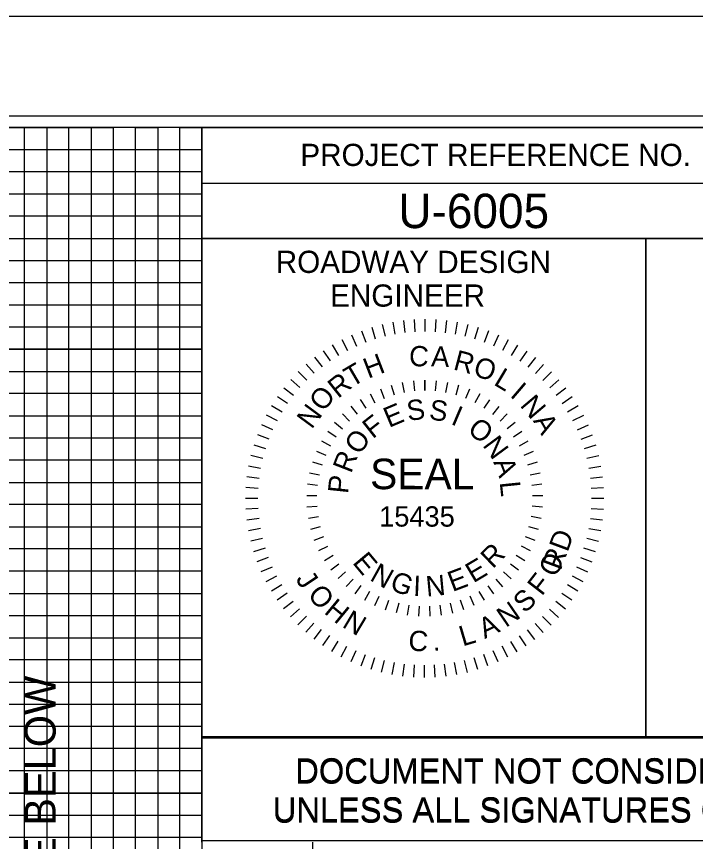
# Model space of a CAD drawing. Extents: x 1626113 to 1628102, y 900759 to 901859.
# Drawn here: x 1627538.1 to 1627691.2, y 901673.3 to 901859.2 of the extents above; entities that cross this region are included whole.
import ezdxf

# ---------------------------------------------------------------- set-up
doc = ezdxf.new("R2010")
doc.units = 0
for name, color, linetype in [('Matchline Text', 7, 'Continuous'), ('Old_Level_21', 7, 'Continuous'), ('Prop Plan Preparation Cover Label', 7, 'Continuous'), ('Sheet Cutting Line CELL', 7, 'Continuous'), ('Sheet Data Field CELL', 7, 'Continuous'), ('Sheet DOT Grid CELL', 7, 'Continuous'), ('Sheet Plot Border Inside CELL', 7, 'Continuous'), ('Sheet Plot Border Outside CELL', 7, 'Continuous'), ('Sheet Profile CELL', 7, 'Continuous'), ('Sheet Profile Grid Major CELL', 7, 'Continuous'), ('Sheet Profile Grid Middle CELL', 7, 'Continuous'), ('Sheet Sticker Exception Certification CELL', 7, 'Continuous')]:
    doc.layers.add(name, color=color, linetype=linetype)

msp = doc.modelspace()

# ---------------------------------------------------------------- linework, layer by layer
at = {"layer": 'Old_Level_21'}
for p, q in [((1627625.33, 901790.68), (1627625.66, 901787.95)), ((1627627.76, 901790.9), (1627627.92, 901788.15)), ((1627630.2, 901790.97), (1627630.2, 901788.22)), ((1627632.64, 901790.89), (1627632.47, 901788.15)), ((1627635.07, 901790.67), (1627634.73, 901787.94)), ((1627618.19, 901789.16), (1627619, 901786.53)), ((1627620.54, 901789.81), (1627621.19, 901787.14)), ((1627622.92, 901790.32), (1627623.41, 901787.61)), ((1627637.48, 901790.3), (1627636.98, 901787.6)), ((1627639.86, 901789.79), (1627639.2, 901787.12)), ((1627642.21, 901789.13), (1627641.39, 901786.5)), ((1627613.63, 901787.44), (1627614.75, 901784.93)), ((1627615.88, 901788.37), (1627616.86, 901785.79)), ((1627644.51, 901788.33), (1627643.53, 901785.76)), ((1627646.76, 901787.39), (1627645.63, 901784.88)), ((1627609.31, 901785.18), (1627610.73, 901782.82)), ((1627611.43, 901786.38), (1627612.71, 901783.93)), ((1627648.95, 901786.32), (1627647.67, 901783.89)), ((1627651.08, 901785.12), (1627649.65, 901782.77)), ((1627607.26, 901783.86), (1627608.82, 901781.59)), ((1627653.12, 901783.79), (1627651.56, 901781.53)), ((1627605.29, 901782.42), (1627606.99, 901780.25)), ((1627655.08, 901782.35), (1627653.38, 901780.18)), ((1627603.42, 901780.86), (1627605.24, 901778.79)), ((1627656.95, 901780.78), (1627655.13, 901778.73)), ((1627601.64, 901779.19), (1627603.58, 901777.24)), ((1627658.73, 901779.11), (1627656.78, 901777.17)), ((1627599.97, 901777.42), (1627602.02, 901775.59)), ((1627622.57, 901776.11), (1627623.22, 901773.91)), ((1627625.07, 901776.72), (1627625.5, 901774.47)), ((1627627.61, 901777.09), (1627627.83, 901774.81)), ((1627630.18, 901777.21), (1627630.18, 901774.92)), ((1627630.18, 901774.92), (1627630.18, 901777.21)), ((1627632.75, 901777.08), (1627632.53, 901774.8)), ((1627635.29, 901776.71), (1627634.85, 901774.46)), ((1627637.79, 901776.09), (1627637.13, 901773.89)), ((1627660.4, 901777.33), (1627658.33, 901775.51)), ((1627598.4, 901775.54), (1627600.56, 901773.84)), ((1627617.81, 901774.18), (1627618.87, 901772.15)), ((1627620.14, 901775.26), (1627621.01, 901773.13)), ((1627640.21, 901775.23), (1627639.34, 901773.11)), ((1627642.54, 901774.14), (1627641.47, 901772.12)), ((1627661.96, 901775.45), (1627659.79, 901773.76)), ((1627596.95, 901773.58), (1627599.21, 901772.02)), ((1627615.59, 901772.88), (1627616.85, 901770.96)), ((1627644.76, 901772.84), (1627643.5, 901770.92)), ((1627663.4, 901773.49), (1627661.13, 901771.93)), ((1627595.63, 901771.54), (1627597.98, 901770.11)), ((1627613.51, 901771.37), (1627614.95, 901769.58)), ((1627646.83, 901771.32), (1627645.39, 901769.54)), ((1627664.72, 901771.44), (1627662.36, 901770.02)), ((1627594.42, 901769.41), (1627596.86, 901768.13)), ((1627611.59, 901769.67), (1627613.19, 901768.02)), ((1627648.75, 901769.62), (1627647.15, 901767.98)), ((1627665.92, 901769.31), (1627663.47, 901768.04)), ((1627593.36, 901767.22), (1627595.86, 901766.09)), ((1627609.83, 901767.79), (1627611.58, 901766.31)), ((1627650.5, 901767.73), (1627648.75, 901766.26)), ((1627666.97, 901767.12), (1627664.47, 901766)), ((1627592.42, 901764.97), (1627594.99, 901763.99)), ((1627608.27, 901765.75), (1627610.15, 901764.44)), ((1627652.06, 901765.69), (1627650.17, 901764.38)), ((1627667.91, 901764.87), (1627665.33, 901763.89)), ((1627606.91, 901763.57), (1627608.91, 901762.45)), ((1627653.41, 901763.5), (1627651.41, 901762.39)), ((1627591.62, 901762.67), (1627594.25, 901761.85)), ((1627605.77, 901761.26), (1627607.87, 901760.34)), ((1627654.55, 901761.19), (1627652.45, 901760.28)), ((1627668.7, 901762.56), (1627666.07, 901761.75)), ((1627590.96, 901760.32), (1627593.63, 901759.66)), ((1627669.35, 901760.21), (1627666.68, 901759.56)), ((1627590.45, 901757.94), (1627593.15, 901757.44)), ((1627604.85, 901758.86), (1627607.03, 901758.15)), ((1627655.46, 901758.79), (1627653.27, 901758.09)), ((1627669.86, 901757.82), (1627667.15, 901757.33)), ((1627590.08, 901755.53), (1627592.81, 901755.19)), ((1627604.17, 901756.38), (1627606.41, 901755.88)), ((1627656.13, 901756.31), (1627653.89, 901755.82)), ((1627670.22, 901755.41), (1627667.49, 901755.09)), ((1627603.74, 901753.85), (1627606.01, 901753.57)), ((1627656.56, 901753.77), (1627654.28, 901753.5)), ((1627589.85, 901753.1), (1627592.6, 901752.93)), ((1627670.44, 901752.99), (1627667.69, 901752.83)), ((1627589.78, 901750.66), (1627592.53, 901750.66)), ((1627603.55, 901751.28), (1627605.84, 901751.22)), ((1627656.74, 901751.21), (1627654.45, 901751.16)), ((1627670.51, 901750.55), (1627667.76, 901750.55)), ((1627589.85, 901748.22), (1627592.59, 901748.38)), ((1627603.6, 901748.71), (1627605.89, 901748.88)), ((1627656.68, 901748.64), (1627654.39, 901748.81)), ((1627670.43, 901748.11), (1627667.69, 901748.28)), ((1627590.07, 901745.79), (1627592.79, 901746.12)), ((1627603.91, 901746.16), (1627606.17, 901746.54)), ((1627654.12, 901746.56), (1627656.38, 901746.17)), ((1627604.46, 901743.65), (1627606.67, 901744.25)), ((1627655.81, 901743.58), (1627653.6, 901744.18)), ((1627670.21, 901745.68), (1627667.48, 901746.02)), ((1627590.43, 901743.38), (1627593.13, 901743.87)), ((1627669.84, 901743.27), (1627667.14, 901743.77)), ((1627590.93, 901741), (1627593.61, 901741.65)), ((1627605.25, 901741.2), (1627607.4, 901742.01)), ((1627655.01, 901741.13), (1627652.86, 901741.95)), ((1627669.33, 901740.89), (1627666.66, 901741.55)), ((1627591.59, 901738.65), (1627594.22, 901739.46)), ((1627606.28, 901738.85), (1627608.33, 901739.86)), ((1627653.97, 901738.78), (1627651.92, 901739.8)), ((1627668.67, 901738.54), (1627666.04, 901739.36)), ((1627592.38, 901736.34), (1627594.95, 901737.32)), ((1627607.52, 901736.6), (1627609.47, 901737.8)), ((1627652.73, 901736.54), (1627650.78, 901737.74)), ((1627667.87, 901736.24), (1627665.3, 901737.22)), ((1627593.31, 901734.09), (1627595.82, 901735.21)), ((1627608.98, 901734.48), (1627610.81, 901735.87)), ((1627651.26, 901734.42), (1627649.44, 901735.81)), ((1627666.93, 901733.99), (1627664.42, 901735.12)), ((1627594.37, 901731.89), (1627596.81, 901733.17)), ((1627610.64, 901732.51), (1627612.32, 901734.07)), ((1627649.6, 901732.46), (1627647.93, 901734.02)), ((1627665.86, 901731.79), (1627663.43, 901733.08)), ((1627595.57, 901729.77), (1627597.92, 901731.19)), ((1627612.47, 901730.72), (1627614, 901732.43)), ((1627647.76, 901730.67), (1627646.24, 901732.38)), ((1627614.48, 901729.1), (1627615.83, 901730.95)), ((1627616.62, 901727.69), (1627617.79, 901729.67)), ((1627643.6, 901727.65), (1627642.44, 901729.63)), ((1627645.75, 901729.06), (1627644.41, 901730.92)), ((1627664.66, 901729.67), (1627662.31, 901731.1)), ((1627596.89, 901727.72), (1627599.16, 901729.28)), ((1627598.33, 901725.76), (1627600.5, 901727.45)), ((1627618.9, 901726.49), (1627619.87, 901728.57)), ((1627621.28, 901725.52), (1627622.05, 901727.68)), ((1627638.94, 901725.49), (1627638.18, 901727.66)), ((1627641.32, 901726.46), (1627640.36, 901728.54)), ((1627663.33, 901727.63), (1627661.07, 901729.19)), ((1627599.89, 901723.88), (1627601.95, 901725.7)), ((1627624.28, 901727.01), (1627623.72, 901724.78)), ((1627626.26, 901724.28), (1627626.6, 901726.55)), ((1627628.82, 901724.03), (1627628.93, 901726.32)), ((1627631.39, 901724.03), (1627631.29, 901726.32)), ((1627633.95, 901724.27), (1627633.62, 901726.54)), ((1627636.47, 901724.76), (1627635.93, 901726.99)), ((1627660.32, 901723.79), (1627658.27, 901725.62)), ((1627661.89, 901725.67), (1627659.72, 901727.36)), ((1627601.56, 901722.1), (1627603.51, 901724.04)), ((1627658.65, 901722.02), (1627656.7, 901723.97)), ((1627603.33, 901720.43), (1627605.16, 901722.48)), ((1627656.87, 901720.35), (1627655.05, 901722.41)), ((1627605.21, 901718.86), (1627606.9, 901721.02)), ((1627654.99, 901718.79), (1627653.3, 901720.96)), ((1627607.17, 901717.41), (1627608.73, 901719.68)), ((1627609.21, 901716.09), (1627610.64, 901718.44)), ((1627650.98, 901716.03), (1627649.56, 901718.38)), ((1627653.03, 901717.35), (1627651.47, 901719.62)), ((1627611.33, 901714.89), (1627612.62, 901717.32)), ((1627613.53, 901713.82), (1627614.66, 901716.32)), ((1627646.66, 901713.77), (1627645.54, 901716.28)), ((1627648.85, 901714.83), (1627647.58, 901717.27)), ((1627615.78, 901712.88), (1627616.76, 901715.45)), ((1627618.08, 901712.08), (1627618.9, 901714.71)), ((1627642.1, 901712.05), (1627641.29, 901714.68)), ((1627644.4, 901712.84), (1627643.43, 901715.41)), ((1627620.43, 901711.42), (1627621.09, 901714.09)), ((1627622.81, 901710.91), (1627623.31, 901713.61)), ((1627625.22, 901710.54), (1627625.56, 901713.27)), ((1627627.65, 901710.31), (1627627.82, 901713.06)), ((1627630.09, 901710.24), (1627630.09, 901712.99)), ((1627632.53, 901710.31), (1627632.37, 901713.05)), ((1627634.95, 901710.53), (1627634.63, 901713.26)), ((1627637.36, 901710.89), (1627636.87, 901713.59)), ((1627639.75, 901711.39), (1627639.1, 901714.07))]:
    msp.add_line(p, q, dxfattribs=at)
at = {"layer": 'Prop Plan Preparation Cover Label'}
for p, q in [((1626329.95, 901829.2), (1627579.95, 901829.2)), ((1627579.95, 901824.2), (1626329.95, 901823.85)), ((1626329.95, 901819.2), (1627579.95, 901819.2)), ((1627579.9, 901699.2), (1626329.95, 901699.2)), ((1627579.95, 901694.2), (1626329.95, 901694.2)), ((1627579.95, 901689.2), (1626329.95, 901689.2)), ((1626329.95, 901679.2), (1627579.95, 901679.2)), ((1627579.95, 901674.2), (1626329.95, 901674.2))]:
    msp.add_line(p, q, dxfattribs=at)
for points in [[(1627534.95, 901334.2), (1627539.95, 901334.2), (1627539.95, 901834.2), (1627544.95, 901834.2), (1627544.95, 901334.2), (1627549.95, 901334.2), (1627549.95, 901834.2), (1627559.95, 901834.2), (1627559.95, 901334.2), (1627564.95, 901334.2), (1627564.95, 901834.2), (1627569.95, 901834.2), (1627569.95, 901334.2), (1627574.95, 901334.2), (1627574.95, 901834.2), (1627584.95, 901834.2)], [(1627579.95, 901814.2), (1626329.95, 901814.2), (1626329.95, 901804.2), (1627579.95, 901804.2)], [(1627579.9, 901799.2), (1626329.95, 901799.2), (1626329.95, 901794.2), (1627579.95, 901794.2)], [(1627579.95, 901789.2), (1626329.95, 901789.2), (1626329.95, 901779.2), (1627579.95, 901779.2)], [(1627579.95, 901774.2), (1626329.95, 901774.2), (1626329.95, 901769.2), (1627579.95, 901769.2)], [(1627579.95, 901764.2), (1626329.95, 901764.2), (1626329.95, 901754.2), (1627579.95, 901754.2)], [(1627579.95, 901749.2), (1626329.95, 901749.2), (1626329.95, 901744.2), (1627579.95, 901744.2)], [(1627579.95, 901739.2), (1626329.95, 901739.2), (1626329.95, 901729.2), (1627579.95, 901729.2)], [(1627579.95, 901724.1), (1626330.05, 901724.1), (1626330.05, 901719.2), (1627579.95, 901719.2)], [(1627579.95, 901714.2), (1626329.95, 901714.2), (1626329.95, 901704.2), (1627579.95, 901704.2)]]:
    msp.add_lwpolyline(points, dxfattribs=at)
at = {"layer": 'Sheet Cutting Line CELL'}
msp.add_line((1627796.95, 901859.2), (1626112.95, 901859.2), dxfattribs=at)
at = {"layer": 'Sheet DOT Grid CELL'}
for p, q in [((1627579.9, 901784.2), (1626279.95, 901784.2)), ((1627579.9, 901734.2), (1626279.95, 901734.2)), ((1627579.95, 901334.2), (1627579.95, 901696.65)), ((1627579.95, 901684.2), (1626279.95, 901684.2))]:
    msp.add_line(p, q, dxfattribs=at)
at = {"layer": 'Sheet Plot Border Inside CELL'}
msp.add_lwpolyline([(1626125.95, 900781.65), (1627792.45, 900781.65), (1627792.45, 901836.75), (1626125.95, 901836.75)], close=True, dxfattribs=at)
at = {"layer": 'Sheet Plot Border Outside CELL'}
msp.add_lwpolyline([(1626112.95, 900759.2), (1627796.95, 900759.2), (1627796.95, 901859.2), (1626112.95, 901859.2)], close=True, dxfattribs=at)
at = {"layer": 'Sheet Profile CELL'}
for p, q in [((1627579.9, 901821.65), (1627779.95, 901821.65)), ((1627679.95, 901809.15), (1627679.95, 901696.7))]:
    msp.add_line(p, q, dxfattribs=at)
for points in [[(1627779.95, 901834.2), (1626279.95, 901834.2), (1626279.95, 900784.2), (1627779.95, 900784.2)], [(1627579.9, 901834.2), (1627779.95, 901834.2), (1627779.95, 901809.15), (1627579.9, 901809.15)], [(1627579.9, 901809.15), (1627679.95, 901809.15), (1627679.95, 901696.65), (1627579.9, 901696.65)], [(1627679.95, 901809.15), (1627779.95, 901809.15), (1627779.95, 901696.65), (1627679.95, 901696.65)]]:
    msp.add_lwpolyline(points, close=True, dxfattribs=at)
at = {"layer": 'Sheet Profile Grid Major CELL'}
for points in [[(1627129.95, 901334.2), (1627179.95, 901334.2), (1627179.95, 901834.2), (1627229.95, 901834.2), (1627229.95, 901334.2), (1627279.95, 901334.2), (1627279.95, 901834.2), (1627329.95, 901834.2), (1627329.95, 901334.2), (1627379.95, 901334.2), (1627379.95, 901834.2), (1627429.95, 901834.2), (1627429.95, 901334.2), (1627479.95, 901334.2), (1627479.95, 901834.2), (1627529.95, 901834.2), (1627529.95, 901334.2), (1627579.95, 901334.2), (1627579.95, 901834.2), (1627606.25, 901834.2)], [(1626279.95, 901784.2), (1627579.95, 901784.2)], [(1627579.95, 901734.2), (1626279.95, 901734.2), (1626279.95, 901684.2), (1627579.95, 901684.2)]]:
    msp.add_lwpolyline(points, dxfattribs=at)
at = {"layer": 'Sheet Profile Grid Middle CELL'}
msp.add_line((1626279.95, 901809.2), (1627579.9, 901809.2), dxfattribs=at)
for points in [[(1627104.95, 901834.2), (1627154.95, 901834.2), (1627154.95, 901334.2), (1627204.95, 901334.2), (1627204.95, 901834.2), (1627254.95, 901834.2), (1627254.95, 901334.2), (1627304.95, 901334.2), (1627304.95, 901834.2), (1627354.95, 901834.2), (1627354.95, 901334.2), (1627404.95, 901334.2), (1627404.95, 901834.2), (1627454.95, 901834.2), (1627454.95, 901334.2), (1627504.95, 901334.2), (1627504.95, 901834.2), (1627554.95, 901834.2), (1627554.95, 901334.2), (1627604.95, 901334.2), (1627604.95, 901673.15)], [(1627579.95, 901759.2), (1626279.95, 901759.2), (1626279.95, 901709.2), (1627579.95, 901709.2)]]:
    msp.add_lwpolyline(points, dxfattribs=at)
at = {"layer": 'Sheet Sticker Exception Certification CELL'}
for p, q in [((1627579.9, 901673.4), (1627579.9, 901696.9)), ((1627579.9, 901696.9), (1627779.93, 901696.9)), ((1627579.9, 901673.4), (1627579.9, 901696.9)), ((1627579.9, 901696.9), (1627779.93, 901696.9)), ((1627579.9, 901673.15), (1627579.9, 901696.65)), ((1627579.9, 901696.65), (1627779.93, 901696.65)), ((1627579.9, 901673.15), (1627579.9, 901696.65)), ((1627579.9, 901696.65), (1627779.93, 901696.65)), ((1627779.93, 901673.4), (1627579.9, 901673.4)), ((1627779.93, 901673.4), (1627579.9, 901673.4))]:
    msp.add_line(p, q, dxfattribs=at)

# ---------------------------------------------------------------- texts
at = {"layer": 'Matchline Text'}
msp.add_text('MATCH LINE -L- STA 50+00.00 SEE BELOW', height=7, rotation=90, dxfattribs=at).set_placement((1627546.95, 901519.45))
at = {"layer": 'Old_Level_21'}
for s, height, rotation, p in [('H', 4.58, 20.9878, (1627617.4, 901777.54)), ('C', 4.58, 357.2771, (1627626.52, 901780.47)), ('A', 4.58, 357.2771, (1627631.53, 901780.37)), ('R', 4.58, 345.2678, (1627636.38, 901779.69)), ('O', 4.58, 342.211, (1627640.82, 901778.36)), ('T', 4.58, 30.4198, (1627613.7, 901775.55)), ('L', 4.58, 329.0747, (1627645.48, 901776.32)), ('R', 4.58, 38.5807, (1627610.62, 901772.99)), ('I', 4.58, 319.4993, (1627649.17, 901773.65)), ('O', 4.58, 51.6375, (1627607.3, 901769.91)), ('N', 4.58, 310.2048, (1627651.46, 901771.49)), ('E', 4.58, 22.8645, (1627622.08, 901766.46)), ('S', 4.58, 7.5683, (1627626.39, 901768.03)), ('S', 4.58, 352.272, (1627630.96, 901768.41)), ('N', 4.58, 53.5969, (1627604.66, 901766.04)), ('I', 4.58, 336.9758, (1627635.83, 901767.41)), ('F', 4.58, 38.1608, (1627618.41, 901763.88)), ('O', 4.58, 321.6795, (1627639.53, 901765.62)), ('A', 4.58, 300.4373, (1627654.48, 901768.1)), ('O', 4.58, 53.457, (1627615.36, 901760.19)), ('N', 4.58, 306.3833, (1627643.05, 901762.55)), ('R', 4.58, 68.7533, (1627613.54, 901756.07)), ('SEAL', 6.878, 359.9202, (1627617.82, 901752.68)), ('A', 4.58, 291.0871, (1627645.56, 901758.79)), ('P', 4.58, 84.0495, (1627612.84, 901751.53)), ('L', 4.58, 275.7908, (1627647.04, 901754.25)), ('15435', 4.582, 359.9202, (1627619.87, 901744.25)), (' RD', 4.582, 69.5926, (1627660.19, 901732.6)), ('E', 4.58, 309.9903, (1627613.7, 901736.07)), ('R', 4.58, 44.4851, (1627645.47, 901734.61)), ('E', 4.58, 30.714, (1627641.1, 901731.43)), ('O ', 4.582, 60.9198, (1627659.52, 901732.57)), ('N', 4.58, 330.8453, (1627617.54, 901732.25)), ('E', 4.58, 20.7281, (1627636.4, 901729.48)), ('J', 4.58, 303.8552, (1627600.91, 901732.35)), ('G', 4.58, 339.6116, (1627622.03, 901730.09)), ('I', 4.58, 357.7064, (1627627.48, 901728.62)), ('N', 4.58, 5.336, (1627630.59, 901728.46)), ('F', 4.58, 52.1272, (1627656.53, 901728.44)), ('O', 4.58, 311.927, (1627603.53, 901728.69)), ('S', 4.58, 43.2446, (1627652.71, 901724.55)), ('H', 4.58, 320.5697, (1627607.26, 901724.83)), ('N', 4.58, 34.362, (1627648.42, 901721.38)), ('N', 4.58, 329.2423, (1627611.32, 901721.73)), ('A', 4.58, 25.5393, (1627643.66, 901718.89)), ('L', 4.58, 16.5368, (1627638.7, 901717.22)), ('C', 4.58, 356.0101, (1627626.34, 901716.34)), ('.', 4.58, 3.7525, (1627632.03, 901716.21))]:
    msp.add_text(s, height=height, rotation=rotation, dxfattribs=at).set_placement(p)
at = {"layer": 'Sheet Data Field CELL'}
msp.add_text('U-6005', height=7.75, dxfattribs=at).set_placement((1627624.19, 901811.51))
at = {"layer": 'Sheet Profile CELL'}
for s, height, p in [('PROJECT REFERENCE NO.', 5.0001, (1627602.11, 901825.51)), ('ROADWAY DESIGN', 5.0001, (1627596.56, 901801.41)), ('ENGINEER', 5, (1627608.81, 901793.81))]:
    msp.add_text(s, height=height, dxfattribs=at).set_placement(p)
at = {"layer": 'Sheet Sticker Exception Certification CELL'}
for s, p in [('DOCUMENT NOT CONSIDERED FINAL', (1627600.97, 901686.55)), ('DOCUMENT NOT CONSIDERED FINAL', (1627600.97, 901686.55)), ('DOCUMENT NOT CONSIDERED FINAL', (1627600.97, 901686.3)), ('DOCUMENT NOT CONSIDERED FINAL', (1627600.97, 901686.3)), ('UNLESS ALL SIGNATURES COMPLETED', (1627595.9, 901677.75)), ('UNLESS ALL SIGNATURES COMPLETED', (1627595.9, 901677.75)), ('UNLESS ALL SIGNATURES COMPLETED', (1627595.9, 901677.5)), ('UNLESS ALL SIGNATURES COMPLETED', (1627595.9, 901677.5))]:
    msp.add_text(s, height=5.5, dxfattribs=at).set_placement(p)

doc.saveas('drawing.dxf')
